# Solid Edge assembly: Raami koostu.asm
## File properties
Author: Türk
Template: iso assembly.asm
Last saved by: Owner
Revision: 22
Application: Solid Edge
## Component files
Poldikoostu7_mir.asm
Piduriketastagu.par
SHKOOSTU.tagu.asm
Taguvedrustus koostu.asm
Keeramismehanismi hammakas.asm
Mootorikoostu.asm
HUB_5.par
HUB_5_esi.par
Poldikoostu7.asm
Kuullaager Esi.asm
Piduriketastagu_mir.par
Kuullaager Tagu.asm
lliliigend.par
ll.par
kardaan.par
esiklaas.par
tagaklaas.par
Kapott.par
raam.par
Esivedrustuse koostu.asm
Tagumised kerepaneelid.par
Vardakoostu.asm
Uks_mir.par
Poldikoostu4.asm
Esituled_mir1.par
tagatuli.par
Esituled.par
Tool_mir.par
Tool.par
Pedaalide koostu.asm
Pidurisupport.par
Liigend2.par
Uks.par
rattakoostu_mir5.asm
Vardakoostu_mir.asm
Esivedrustuse koostu_mir.asm
Poldikoostu4_mir.asm
re.par
SHKOOSTU.asm
ljepaneelid_mir3.par
ljepaneelid.par
rand.par
Pidurisupport_mir1.par
SHKOOSTU_mir2.asm
Rooli koostu.asm
Piduriketastagu_mir2.par
Taguvedrustus koostu_mir4.asm
SHKOOSTU.tagu_mir1.asm
Poldikoostu4_mir1.asm
rattakoostu_mir4.asm
Poldikoostu4_mir2.asm
Pidurisupport_mir3.par
rattakoostu.asm
Piduriketastagu_mir1.par
Vardakoostu_mir1.asm
Poldikoostu7_mir1.asm
plik.asm
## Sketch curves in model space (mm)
circle centre (400, 1100, 450) radius 40
line (528.4665, 900, -65) -> (528.4665, 1075, -65)
line (324.3116, 900, -65) -> (324.3116, 1075, -65)
line (538.4665, 900, -65) -> (315.8824, 900, -65)
line (148.9201, 2197.09, -75) -> (543.2456, 2197.09, -75)
line (543.2456, 2197.09, -75) -> (543.2456, 1666.9703, -75)
line (543.2456, 1666.9703, -75) -> (148.9201, 1666.9703, -75)
line (148.9201, 1666.9703, -75) -> (148.9201, 2197.09, -75)
circle centre (-509.1669, -725, 165.798) radius 70
arc centre (-509.1669, -725, 165.798) radius 70 from (-498.9283, -725, 235.0452) through (-531.0491, -725, 232.2899) to (-558.5284, -725, 215.431)
arc centre (-509.1669, -725, 165.798) radius 70 from (-498.9283, -725, 235.0452) through (-439.1669, -725, 165.798) to (-498.9283, -725, 96.5508)
arc centre (-509.1669, -725, 165.798) radius 70 from (-558.5284, -725, 116.1649) through (-531.0491, -725, 99.3061) to (-498.9283, -725, 96.5508)
arc centre (-509.1669, -725, 165.798) radius 70 from (-558.5284, -725, 116.1649) through (-579.1371, -725, 167.841) to (-558.5284, -725, 215.431)
arc centre (-658.1579, 3220, 265.0419) radius 65 from (-658.1579, 3220, 330.0419) through (-723.1294, 3220, 263.1157) to (-658.1579, 3220, 200.0419)
line (-658.1579, 3220, 200.0419) -> (-318.1579, 3220, 200.0419)
line (-318.1579, 3220, 200.0419) -> (-318.1579, 3220, 330.0419)
line (-318.1579, 3220, 330.0419) -> (-658.1579, 3220, 330.0419)
arc centre (529.3774, 2420, 550) radius 60 from (588.9141, 2427.4421, 550) through (567.7679, 2466.1104, 550) to (529.3774, 2480, 550)
line (529.3774, 2480, 550) -> (-529.3774, 2480, 550)
arc centre (-529.3774, 2420, 550) radius 60 from (-529.3774, 2480, 550) through (-570.37, 2463.8133, 550) to (-588.9141, 2427.4421, 550)
arc centre (-529.3774, 2420, 550) radius 60 from (-529.3774, 2480, 550) through (-570.37, 2463.8133, 550) to (-588.9141, 2427.4421, 550)
line (529.3774, 2480, 550) -> (-529.3774, 2480, 550)
arc centre (529.3774, 2420, 550) radius 60 from (588.9141, 2427.4421, 550) through (567.7679, 2466.1104, 550) to (529.3774, 2480, 550)
line (604.4723, 2302.9768, 550) -> (588.9141, 2427.4421, 550)
line (601.8444, 2300, 550) -> (604.4723, 2302.9768, 550)
line (645.1556, 2300, 550) -> (601.8444, 2300, 550)
line (645.1556, 2300, 550) -> (628.6052, 2432.4035, 550)
arc centre (529.3774, 2420, 550) radius 100 from (628.6052, 2432.4035, 550) through (593.3616, 2496.8507, 550) to (529.3774, 2520, 550)
line (529.3774, 2520, 550) -> (-529.3774, 2520, 550)
arc centre (-529.3774, 2420, 550) radius 100 from (-529.3774, 2520, 550) through (-597.6984, 2493.0222, 550) to (-628.6052, 2432.4035, 550)
line (-628.6052, 2432.4035, 550) -> (-645.1556, 2300, 550)
line (-588.9141, 2427.4421, 550) -> (-604.4723, 2302.9768, 550)
line (-604.4723, 2302.9768, 550) -> (-601.8444, 2300, 550)
line (-601.8444, 2300, 550) -> (-645.1556, 2300, 550)
line (-600, 2300, 550) -> (-588.9141, 2427.4421, 550)
line (-600, 2300, 550) -> (-600, 2100, 550)
line (-600, 2100, 550) -> (-623.9996, 2100, 550)
line (588.9141, 2427.4421, 550) -> (600, 2300, 550)
line (600, 2300, 550) -> (600, 2100, 550)
line (623.9996, 2100, 550) -> (600, 2100, 550)
line (623.9996, 2300, 550) -> (623.9996, 2100, 550)
line (623.9996, 2300, 550) -> (650, 2300, 550)
line (650, 2300, 550) -> (650, 2339.4268, 550)
arc centre (410, 2339.4268, 550) radius 240 from (650, 2339.4268, 550) through (644.1493, 2392.0966, 550) to (626.8825, 2442.1984, 550)
arc centre (529.3774, 2420, 550) radius 100 from (626.8825, 2442.1984, 550) through (612.2644, 2475.9442, 550) to (586.4361, 2502.1237, 550)
arc centre (410, 2339.4268, 550) radius 240 from (586.4361, 2502.1237, 550) through (577.5031, 2511.3067, 550) to (568.0927, 2520, 550)
line (-568.0927, 2520, 550) -> (568.0927, 2520, 550)
arc centre (-410, 2339.4268, 550) radius 240 from (-568.0927, 2520, 550) through (-577.5031, 2511.3067, 550) to (-586.4361, 2502.1237, 550)
arc centre (-529.3774, 2420, 550) radius 100 from (-586.4361, 2502.1237, 550) through (-612.2644, 2475.9442, 550) to (-626.8825, 2442.1984, 550)
arc centre (-410, 2339.4268, 550) radius 240 from (-626.8825, 2442.1984, 550) through (-644.1493, 2392.0966, 550) to (-650, 2339.4268, 550)
line (-650, 2339.4268, 550) -> (-650, 2300, 550)
line (-650, 2300, 550) -> (-623.9996, 2300, 550)
line (-623.9996, 2300, 550) -> (-623.9996, 2100, 550)
line (-4.8152, 1352.224, -75) -> (-4.8252, 1536.8657, -75)
line (10.1828, 1388.157, -75) -> (-4.8172, 1388.1562, -75)
line (10.1839, 1367.8395, -75) -> (10.1828, 1388.157, -75)
line (10.185, 1348.4746, -75) -> (10.1839, 1367.8395, -75)
line (10.1861, 1328.157, -75) -> (10.185, 1348.4746, -75)
line (-4.815, 1348.4738, -75) -> (-4.8161, 1367.8387, -75)
line (-4.815, 1348.4738, -75) -> (-4.8139, 1328.1562, -75)
line (-4.8139, 1328.1562, -75) -> (10.1861, 1328.157, -75)
arc centre (-353.9193, -725, 148.1276) radius 46.25 from (-369.2539, -725, 191.7614) through (-366.3147, -725, 103.5696) to (-318.2546, -725, 177.5741)
line (0, 2520, 550) -> (0, 2520, 450)
line (0, 2295, 150) -> (0, 2520, 450)
line (0, 2295, 450) -> (0, 2295, 150)
line (0, 2520, 450) -> (0, 2295, 450)
circle centre (400, 1100, 450) radius 40
circle centre (-625, 1100, -125) radius 25
circle centre (-625, 1100, 425) radius 25
circle centre (625, 1100, 425) radius 25
circle centre (625, 1100, -125) radius 25
line (-600, 1100, 400) -> (600, 1100, 400)
line (-600, 1100, 400) -> (600, 1100, 400)
line (636.9998, 1100, 550) -> (650, 1100, 450)
line (591.886, 1100, 731.4928) -> (636.9998, 1100, 550)
arc centre (349.269, 1100, 671.1853) radius 250 from (377.4735, 1100, 919.5892) through (519.499, 1100, 854.2747) to (591.886, 1100, 731.4928)
line (100, 1100, 951.0944) -> (377.4735, 1100, 919.5892)
line (100, 1100, 951.0944) -> (100, 1100, 948.0751)
line (612.3929, 1100, 545.358) -> (624.7896, 1100, 450)
line (567.6243, 1100, 725.462) -> (612.3929, 1100, 545.358)
arc centre (349.269, 1100, 671.1853) radius 225 from (374.6531, 1100, 894.7488) through (502.476, 1100, 835.9658) to (567.6243, 1100, 725.462)
line (97.1616, 1100, 926.256) -> (374.6531, 1100, 894.7488)
line (97.1616, 1100, 926.256) -> (100, 1100, 929.0944)
line (100, 1100, 929.0944) -> (100, 1100, 948.0751)
spline (750.0274, 1100, 149.9987) -> (739.1023, 1100, 317.8977) -> (655, 1100, 444.6388)
arc centre (749.9141, 1100, 145) radius 5 from (750.0274, 1100, 149.9987) through (753.6329, 1100, 148.3423) to (754.9125, 1100, 144.8721)
spline (754.9125, 1100, 144.8721) -> (743.8572, 1100, 319.9786) -> (646.9489, 1100, 450.1987)
line (646.9489, 1100, 450.1987) -> (650, 1100, 450)
line (600, 1100, 400) -> (600, 1100, 145)
arc centre (605, 1100, 145) radius 5 from (600, 1100, 145) through (601.5688, 1100, 148.6369) to (605, 1100, 150)
line (605, 1100, 150) -> (655, 1100, 150)
line (655, 1100, 444.6388) -> (655, 1100, 150)
line (-655, 1100, 444.6388) -> (-655, 1100, 150)
line (-605, 1100, 150) -> (-655, 1100, 150)
arc centre (-605, 1100, 145) radius 5 from (-600, 1100, 145) through (-601.5688, 1100, 148.6369) to (-605, 1100, 150)
line (-600, 1100, 145) -> (-600, 1100, 400)
spline (-646.9489, 1100, 450.1987) -> (-743.8572, 1100, 319.9786) -> (-754.9125, 1100, 144.8721)
arc centre (-749.9141, 1100, 145) radius 5 from (-750.0274, 1100, 149.9987) through (-753.6329, 1100, 148.3423) to (-754.9125, 1100, 144.8721)
spline (-750.0274, 1100, 149.9987) -> (-739.1023, 1100, 317.8977) -> (-655, 1100, 444.6388)
line (-650, 1100, 450) -> (-646.9489, 1100, 450.1987)
line (-624.7896, 1100, 450) -> (-612.3929, 1100, 545.358)
line (-612.3929, 1100, 545.358) -> (-567.6243, 1100, 725.462)
arc centre (-349.269, 1100, 671.1853) radius 225 from (-567.6243, 1100, 725.462) through (-492.6986, 1100, 844.5431) to (-374.6531, 1100, 894.7488)
line (-374.6531, 1100, 894.7488) -> (-97.1616, 1100, 926.256)
line (-100, 1100, 929.0944) -> (-97.1616, 1100, 926.256)
line (-637.0219, 1100, 549.8297) -> (-650, 1100, 450)
arc centre (-634.047, 1100, 549.443) radius 3 from (-636.9584, 1100, 550.1667) through (-636.995, 1100, 549.9991) to (-637.0219, 1100, 549.8297)
line (-591.886, 1100, 731.4928) -> (-636.9584, 1100, 550.1667)
arc centre (-349.269, 1100, 671.1853) radius 250 from (-377.4735, 1100, 919.5892) through (-519.499, 1100, 854.2747) to (-591.886, 1100, 731.4928)
line (-100, 1100, 951.0944) -> (-377.4735, 1100, 919.5892)
line (-100, 1100, 948.0751) -> (-100, 1100, 951.0944)
line (-100, 1100, 948.0751) -> (-100, 1100, 929.0944)
line (120, 1100, 450) -> (-624.7896, 1100, 450)
line (120, 1100, 450) -> (377.1429, 1100, 526.6652)
arc centre (400, 1100, 450) radius 80 from (377.1429, 1100, 526.6652) through (411.7445, 1100, 529.1332) to (444.1379, 1100, 516.7221)
line (444.1379, 1100, 516.7221) -> (544.7336, 1100, 450.1763)
arc centre (487.8583, 1100, 364.1994) radius 103.0865 from (544.7336, 1100, 450.1763) through (544.8664, 1100, 450.0882) to (544.9991, 1100, 450)
line (624.7896, 1100, 450) -> (544.9991, 1100, 450)
spline (750.0203, 1100, 149.6455) -> (739.1266, 1100, 317.7238) -> (655, 1100, 444.6388)
line (655, 1100, 444.6388) -> (655, 1100, 149.9823)
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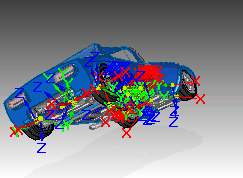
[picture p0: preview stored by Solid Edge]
